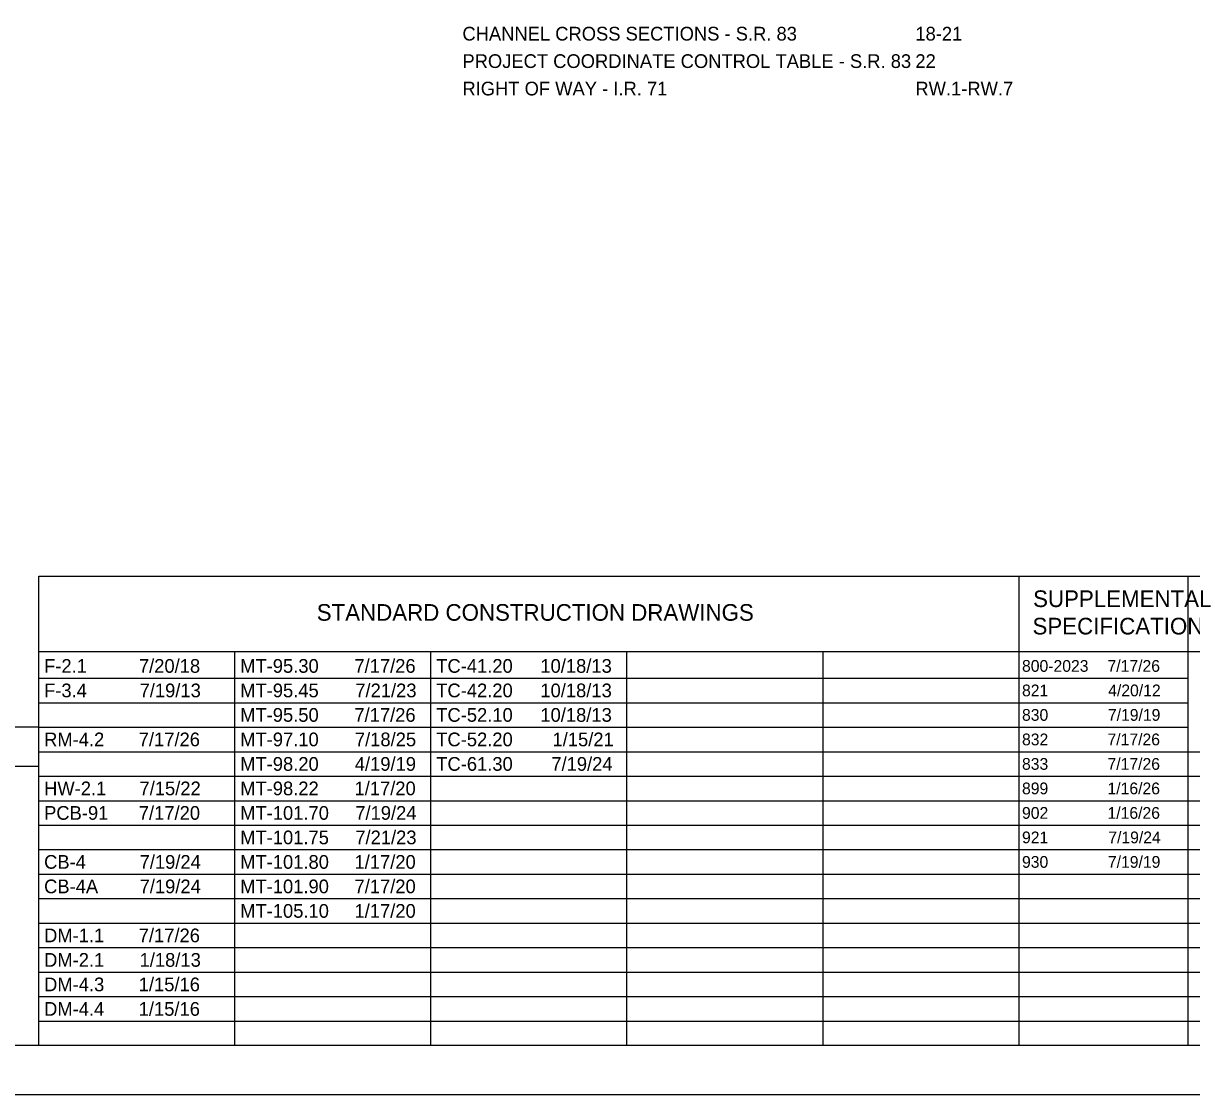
# Model space of a CAD drawing. Extents: x 0 to 34, y 0 to 22.
# Drawn here: x 9.99 to 21.91, y 0 to 10.93 of the extents above; entities that cross this region are included whole.
import ezdxf

# ---------------------------------------------------------------- set-up
doc = ezdxf.new("R2010")
doc.units = 0
for name, color, linetype in [('SH_Border', 7, 'Continuous'), ('SH_Cut_Line', 7, 'Continuous'), ('SH_Data', 7, 'Continuous'), ('SH_Text', 7, 'Continuous')]:
    doc.layers.add(name, color=color, linetype=linetype)

msp = doc.modelspace()

# ---------------------------------------------------------------- linework, layer by layer
at = {"layer": 'SH_Border'}
msp.add_lwpolyline([(1.5, 21.5), (33.5, 21.5), (33.5, 0.5), (1.5, 0.5)], close=True, dxfattribs=at)
at = {"layer": 'SH_Cut_Line'}
msp.add_lwpolyline([(0, 0), (34, 0), (34, 22), (0, 22)], close=True, dxfattribs=at)
at = {"layer": 'SH_Data'}
for p, q in [((10.15, 5.292), (23.6, 5.292)), ((10.15, 0.5), (10.15, 5.292)), ((20.15, 0.5), (20.15, 5.292)), ((21.875, 0.5), (21.875, 5.292)), ((10.15, 4.521), (23.6, 4.521)), ((12.15, 0.5), (12.15, 4.521)), ((14.15, 0.5), (14.15, 4.521)), ((16.15, 0.5), (16.15, 4.521)), ((18.15, 0.5), (18.15, 4.521)), ((10.15, 4.25), (21.875, 4.25)), ((10.15, 4), (21.875, 4)), ((10.15, 3.75), (7.35, 3.75)), ((10.15, 3.75), (21.875, 3.75)), ((10.15, 0.5), (10.15, 3.75)), ((10.15, 3.5), (23.6, 3.5)), ((10.15, 3.35), (7.35, 3.35)), ((10.15, 3.25), (23.6, 3.25)), ((10.15, 3), (23.6, 3)), ((10.15, 2.75), (23.6, 2.75)), ((10.15, 2.5), (23.6, 2.5)), ((10.15, 2.25), (23.6, 2.25)), ((10.15, 2), (23.6, 2)), ((10.15, 1.75), (23.6, 1.75)), ((10.15, 1.5), (23.6, 1.5)), ((10.15, 1.25), (23.6, 1.25)), ((10.15, 1), (23.6, 1)), ((10.15, 0.75), (23.6, 0.75)), ((10.15, 0.5), (7.35, 0.5))]:
    msp.add_line(p, q, dxfattribs=at)

# ---------------------------------------------------------------- texts
at = {"layer": 'SH_Text'}
for s, height, p in [('CHANNEL CROSS SECTIONS - S.R. 83', 0.14, (14.472, 10.757)), ('18-21', 0.14, (19.092, 10.757)), ('PROJECT COORDINATE CONTROL TABLE - S.R. 83', 0.14, (14.472, 10.477)), ('22', 0.14, (19.092, 10.477)), ('RIGHT OF WAY - I.R. 71', 0.14, (14.472, 10.197)), ('RW.1-RW.7', 0.14, (19.092, 10.197)), ('SUPPLEMENTAL', 0.17, (20.293, 4.976)), ('STANDARD CONSTRUCTION DRAWINGS', 0.17, (12.986, 4.836)), ('SPECIFICATIONS', 0.17, (20.287, 4.696)), ('F-2.1', 0.14, (10.205, 4.305)), ('7/20/18', 0.14, (11.172, 4.305)), ('MT-95.30', 0.14, (12.205, 4.305)), ('7/17/26', 0.14, (13.37, 4.305)), ('TC-41.20', 0.14, (14.205, 4.305)), ('10/18/13', 0.14, (15.267, 4.305)), ('800-2023', 0.12, (20.18, 4.315)), ('7/17/26', 0.12, (21.052, 4.315)), ('F-3.4', 0.14, (10.205, 4.055)), ('7/19/13', 0.14, (11.179, 4.055)), ('MT-95.45', 0.14, (12.205, 4.055)), ('7/21/23', 0.14, (13.379, 4.055)), ('TC-42.20', 0.14, (14.205, 4.055)), ('10/18/13', 0.14, (15.267, 4.055)), ('821', 0.12, (20.18, 4.065)), ('4/20/12', 0.12, (21.059, 4.065)), ('MT-95.50', 0.14, (12.205, 3.805)), ('7/17/26', 0.14, (13.37, 3.805)), ('TC-52.10', 0.14, (14.205, 3.805)), ('10/18/13', 0.14, (15.267, 3.805)), ('830', 0.12, (20.18, 3.815)), ('7/19/19', 0.12, (21.056, 3.815)), ('RM-4.2', 0.14, (10.205, 3.555)), ('7/17/26', 0.14, (11.17, 3.555)), ('MT-97.10', 0.14, (12.205, 3.555)), ('7/18/25', 0.14, (13.375, 3.555)), ('TC-52.20', 0.14, (14.205, 3.555)), ('1/15/21', 0.14, (15.391, 3.555)), ('832', 0.12, (20.18, 3.565)), ('7/17/26', 0.12, (21.052, 3.565)), ('MT-98.20', 0.14, (12.205, 3.305)), ('4/19/19', 0.14, (13.374, 3.305)), ('TC-61.30', 0.14, (14.205, 3.305)), ('7/19/24', 0.14, (15.379, 3.305)), ('833', 0.12, (20.18, 3.315)), ('7/17/26', 0.12, (21.052, 3.315)), ('HW-2.1', 0.14, (10.205, 3.055)), ('7/15/22', 0.14, (11.178, 3.055)), ('MT-98.22', 0.14, (12.205, 3.055)), ('1/17/20', 0.14, (13.371, 3.055)), ('899', 0.12, (20.18, 3.065)), ('1/16/26', 0.12, (21.052, 3.065)), ('PCB-91', 0.14, (10.205, 2.805)), ('7/17/20', 0.14, (11.171, 2.805)), ('MT-101.70', 0.14, (12.205, 2.805)), ('7/19/24', 0.14, (13.379, 2.805)), ('902', 0.12, (20.18, 2.815)), ('1/16/26', 0.12, (21.052, 2.815)), ('MT-101.75', 0.14, (12.205, 2.555)), ('7/21/23', 0.14, (13.379, 2.555)), ('921', 0.12, (20.18, 2.565)), ('7/19/24', 0.12, (21.06, 2.565)), ('CB-4', 0.14, (10.205, 2.305)), ('7/19/24', 0.14, (11.179, 2.305)), ('MT-101.80', 0.14, (12.205, 2.305)), ('1/17/20', 0.14, (13.371, 2.305)), ('930', 0.12, (20.18, 2.315)), ('7/19/19', 0.12, (21.056, 2.315)), ('CB-4A', 0.14, (10.205, 2.055)), ('7/19/24', 0.14, (11.179, 2.055)), ('MT-101.90', 0.14, (12.205, 2.055)), ('7/17/20', 0.14, (13.371, 2.055)), ('MT-105.10', 0.14, (12.205, 1.805)), ('1/17/20', 0.14, (13.371, 1.805)), ('DM-1.1', 0.14, (10.205, 1.555)), ('7/17/26', 0.14, (11.17, 1.555)), ('DM-2.1', 0.14, (10.205, 1.305)), ('1/18/13', 0.14, (11.179, 1.305)), ('DM-4.3', 0.14, (10.205, 1.055)), ('1/15/16', 0.14, (11.17, 1.055)), ('DM-4.4', 0.14, (10.205, 0.805)), ('1/15/16', 0.14, (11.17, 0.805))]:
    msp.add_text(s, height=height, dxfattribs=at).set_placement(p)

doc.saveas('drawing.dxf')
